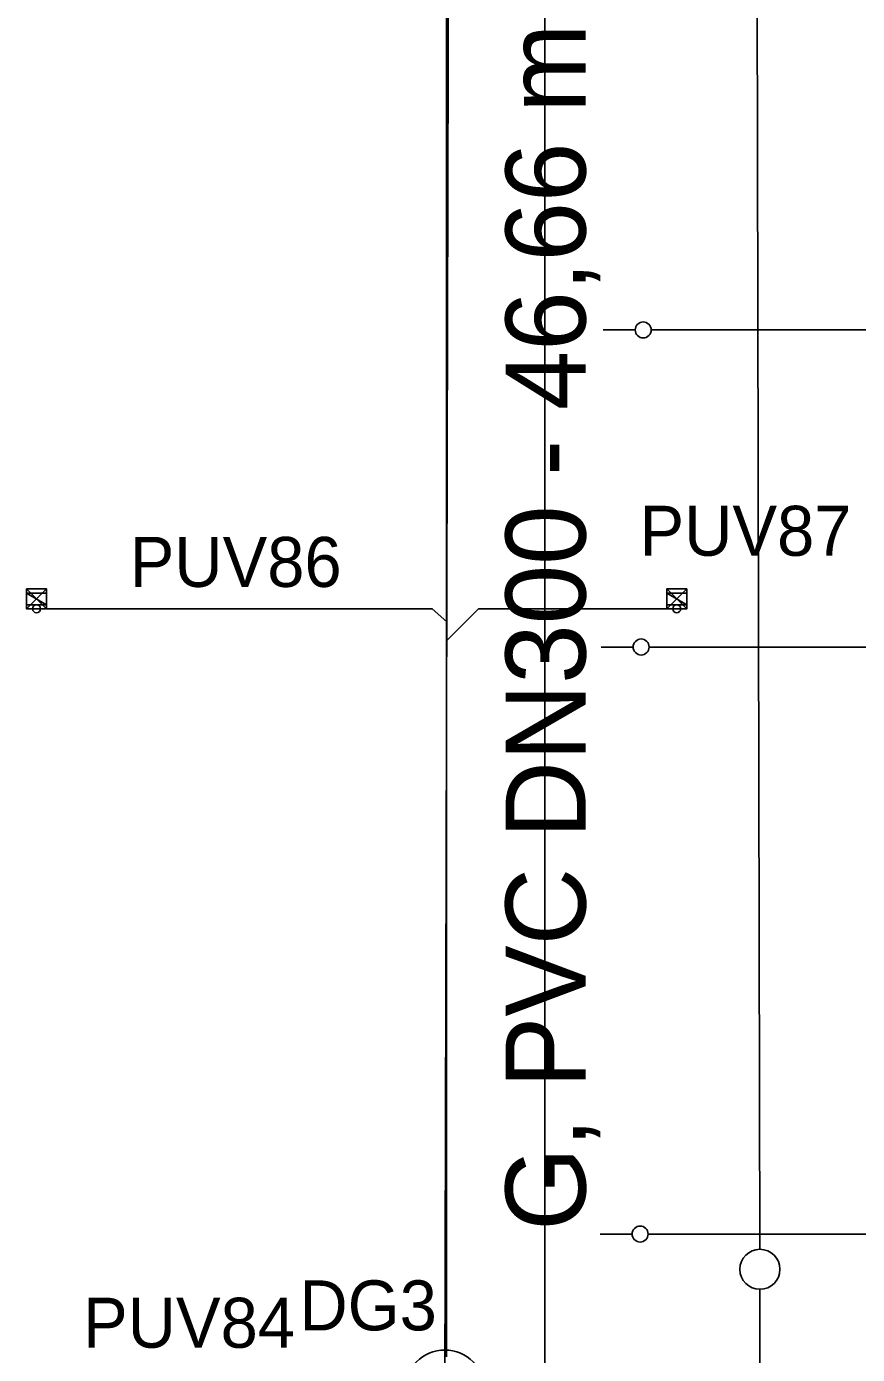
# Model space of a CAD drawing. Extents: x -264234 to -263604, y -1242346 to -1242049.
# Drawn here: x -263937.09 to -263916.33, y -1242154.19 to -1242121 of the extents above; entities that cross this region are included whole.
import ezdxf

# ---------------------------------------------------------------- set-up
doc = ezdxf.new("R2010")
doc.units = 0
for name, color, linetype in [('KFA_DAZDOVA_KANALIZACIA_vetva_G', 7, 'Continuous'), ('KFA_DAZDOVA_KANALIZACIA_vetva_G_popis', 7, 'Continuous'), ('KFA_JESTV_IS_DSP_-_KANAL_DAZD', 7, 'Continuous'), ('KFA_SITUACIA_DSP', 7, 'Continuous'), ('KFA_SO_40-2-II_DK_PRIPOJKY_UV_PROJEKT', 7, 'Continuous'), ('KFA_SO_40-2-II_DK_PRIPOJKY_UV_PROJEKT_popis', 7, 'Continuous'), ('KFA_SO_40-2-II_DK_UV_PROJEKT', 7, 'Continuous')]:
    doc.layers.add(name, color=color, linetype=linetype)

msp = doc.modelspace()

# ---------------------------------------------------------------- linework, layer by layer
at = {"layer": 'KFA_DAZDOVA_KANALIZACIA_vetva_G'}
msp.add_lwpolyline([(-263926.523, -1242108.42), (-263926.639, -1242155.082), (-263926.646, -1242205.066)], dxfattribs=at)
msp.add_circle((-263926.639, -1242155.082), 1, dxfattribs=at)
at = {"layer": 'KFA_JESTV_IS_DSP_-_KANAL_DAZD'}
for p, q in [((-263918.855, -1242107.583), (-263918.765, -1242151.564)), ((-263918.764, -1242152.564), (-263918.757, -1242196.225))]:
    msp.add_line(p, q, dxfattribs=at)
msp.add_circle((-263918.764, -1242152.064), 0.5, dxfattribs=at)
at = {"layer": 'KFA_SITUACIA_DSP'}
for p, q in [((-263924.143, -1242082.64), (-263924.143, -1242185.14)), ((-263926.593, -1242107.902), (-263926.593, -1242154.252)), ((-263926.593, -1242107.902), (-263926.593, -1242154.252)), ((-263921.881, -1242128.582), (-263922.681, -1242128.582)), ((-263917.093, -1242128.582), (-263921.481, -1242128.582)), ((-263909.043, -1242128.582), (-263917.093, -1242128.582)), ((-263937.092, -1242135.452), (-263937.092, -1242135.162)), ((-263937.092, -1242135.162), (-263936.592, -1242135.162)), ((-263936.592, -1242135.452), (-263937.092, -1242135.162)), ((-263936.592, -1242135.452), (-263937.092, -1242135.162)), ((-263937.092, -1242135.162), (-263937.092, -1242135.452)), ((-263936.592, -1242135.162), (-263936.592, -1242135.452)), ((-263921.093, -1242135.452), (-263921.093, -1242135.162)), ((-263921.093, -1242135.162), (-263920.593, -1242135.162)), ((-263920.593, -1242135.452), (-263921.093, -1242135.162)), ((-263920.593, -1242135.452), (-263921.093, -1242135.162)), ((-263921.093, -1242135.162), (-263921.093, -1242135.452)), ((-263920.593, -1242135.162), (-263920.593, -1242135.452)), ((-263936.592, -1242135.452), (-263937.092, -1242135.452)), ((-263937.092, -1242135.452), (-263936.592, -1242135.452)), ((-263920.593, -1242135.452), (-263921.093, -1242135.452)), ((-263921.093, -1242135.452), (-263920.593, -1242135.452)), ((-263936.743, -1242135.552), (-263926.953, -1242135.552)), ((-263926.953, -1242135.552), (-263926.592, -1242135.877)), ((-263925.797, -1242135.552), (-263926.592, -1242136.347)), ((-263920.943, -1242135.552), (-263925.797, -1242135.552)), ((-263921.932, -1242136.507), (-263922.732, -1242136.507)), ((-263917.093, -1242136.507), (-263921.532, -1242136.507)), ((-263917.093, -1242136.507), (-263914.143, -1242136.507)), ((-263921.957, -1242151.182), (-263922.757, -1242151.182)), ((-263917.093, -1242151.182), (-263921.557, -1242151.182)), ((-263914.143, -1242151.182), (-263917.093, -1242151.182))]:
    msp.add_line(p, q, dxfattribs=at)
for centre, radius in [((-263921.681, -1242128.582), 0.2), ((-263936.843, -1242135.552), 0.1), ((-263920.843, -1242135.552), 0.1), ((-263921.732, -1242136.507), 0.2), ((-263921.757, -1242151.182), 0.2)]:
    msp.add_circle(centre, radius, dxfattribs=at)
at = {"layer": 'KFA_SO_40-2-II_DK_PRIPOJKY_UV_PROJEKT'}
for points in [[(-263936.743, -1242135.552), (-263926.953, -1242135.552), (-263926.592, -1242135.877)], [(-263920.943, -1242135.552), (-263925.797, -1242135.552), (-263926.592, -1242136.347)]]:
    msp.add_lwpolyline(points, dxfattribs=at)
at = {"layer": 'KFA_SO_40-2-II_DK_UV_PROJEKT'}
for points in [[(-263937.092, -1242135.557), (-263937.092, -1242135.057), (-263936.592, -1242135.057), (-263936.592, -1242135.557), (-263937.092, -1242135.557), (-263936.592, -1242135.057), (-263937.092, -1242135.057), (-263936.592, -1242135.557)], [(-263921.093, -1242135.557), (-263921.093, -1242135.057), (-263920.593, -1242135.057), (-263920.593, -1242135.557), (-263921.093, -1242135.557), (-263920.593, -1242135.057), (-263921.093, -1242135.057), (-263920.593, -1242135.557)]]:
    msp.add_lwpolyline(points, dxfattribs=at)

# ---------------------------------------------------------------- texts
at = {"layer": 'KFA_DAZDOVA_KANALIZACIA_vetva_G_popis'}
msp.add_text('G, PVC DN300 - 46,66 m', height=2, rotation=90, dxfattribs=at).set_placement((-263923.121, -1242151.099))
msp.add_text('DG3', height=1.25, dxfattribs=at).set_placement((-263930.274, -1242153.591))
at = {"layer": 'KFA_SO_40-2-II_DK_PRIPOJKY_UV_PROJEKT_popis'}
for s, p in [('PUV87', (-263921.772, -1242134.227)), ('PUV86', (-263934.514, -1242135.005)), ('PUV84', (-263935.68, -1242154.025))]:
    msp.add_text(s, height=1.25, dxfattribs=at).set_placement(p)

doc.saveas('drawing.dxf')
